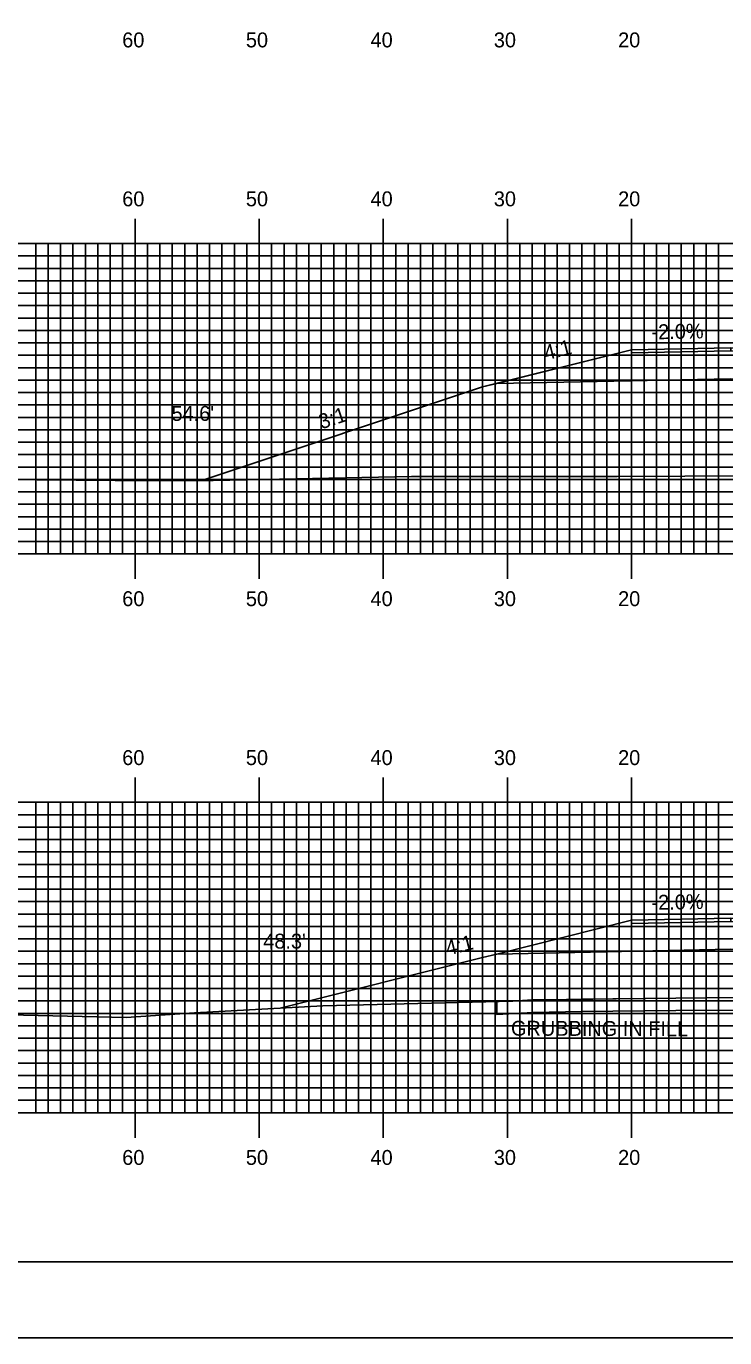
# Model space of a CAD drawing. Extents: x 1814915 to 1815259, y 442591 to 442811.
# Drawn here: x 1815012.3 to 1815068.5, y 442590.5 to 442696.2 of the extents above; entities that cross this region are included whole.
import ezdxf

# ---------------------------------------------------------------- set-up
doc = ezdxf.new("R2010")
doc.units = 0
for name, color, linetype in [('ANNOTATION', 7, 'Continuous'), ('BORDER', 7, 'Continuous'), ('D_Roadway_Centerline', 7, 'Continuous'), ('D_Roadway_Edge_Shoulder', 7, 'Continuous'), ('D_Roadway_SlopeLines', 7, 'Continuous'), ('D_Roadway_SubGrade', 7, 'Continuous'), ('D_Text_Standard', 7, 'Continuous'), ('GRUBBING IN FILL', 7, 'Continuous'), ('H_V ANNOTATION', 7, 'Continuous'), ('MAJOR', 7, 'Continuous'), ('MINOR', 7, 'Continuous'), ('PLOT BOUNDARY', 7, 'Continuous'), ('S_Roadway_Centerline', 7, 'Continuous')]:
    doc.layers.add(name, color=color, linetype=linetype)

msp = doc.modelspace()

# ---------------------------------------------------------------- linework, layer by layer
at = {"layer": 'BORDER'}
msp.add_lwpolyline([(1814931.42, 442596.67), (1815251.42, 442596.67), (1815251.42, 442806.67), (1814931.42, 442806.67)], close=True, dxfattribs=at)
at = {"layer": 'D_Roadway_Centerline'}
for points in [[(1815026.39, 442659.58), (1815049.02, 442667.12), (1815050.15, 442667.4), (1815061.02, 442670.12), (1815069.02, 442670.28), (1815081.02, 442669.7), (1815093.02, 442669.13), (1815101.02, 442668.74), (1815113.02, 442665.74), (1815113.4, 442665.65), (1815128.52, 442660.58)], [(1815032.71, 442617.09), (1815049.02, 442621.17), (1815050.15, 442621.45), (1815061.02, 442624.17), (1815069.02, 442624.33), (1815081.02, 442623.75), (1815093.02, 442623.17), (1815101.02, 442622.79), (1815113.4, 442619.7), (1815123.45, 442617.18)]]:
    msp.add_lwpolyline(points, dxfattribs=at)
at = {"layer": 'D_Roadway_Edge_Shoulder'}
for points in [[(1815069.02, 442670.28), (1815061.02, 442670.12), (1815061.02, 442669.87), (1815069.02, 442670.03)], [(1815069.02, 442624.33), (1815061.02, 442624.17), (1815061.02, 442623.92), (1815069.02, 442624.08)]]:
    msp.add_lwpolyline(points, close=True, dxfattribs=at)
at = {"layer": 'D_Roadway_SlopeLines'}
for points in [[(1815061.02, 442670.12), (1815049.02, 442667.12), (1815026.39, 442659.58)], [(1815061.02, 442624.17), (1815050.15, 442621.45), (1815049.02, 442621.17), (1815032.71, 442617.09)]]:
    msp.add_lwpolyline(points, dxfattribs=at)
at = {"layer": 'D_Roadway_SubGrade'}
for points in [[(1815069.02, 442667.78), (1815050.15, 442667.4), (1815061.02, 442670.12), (1815061.02, 442669.87), (1815069.02, 442670.03), (1815081.02, 442669.45), (1815093.02, 442668.88), (1815101.02, 442668.49), (1815101.02, 442668.74), (1815113.4, 442665.65), (1815093.02, 442666.63), (1815081.02, 442667.2)], [(1815069.02, 442621.83), (1815050.15, 442621.45), (1815061.02, 442624.17), (1815061.02, 442623.92), (1815069.02, 442624.08), (1815081.02, 442623.5), (1815093.02, 442622.92), (1815101.02, 442622.54), (1815101.02, 442622.79), (1815113.4, 442619.7), (1815093.02, 442620.67), (1815081.02, 442621.25)]]:
    msp.add_lwpolyline(points, close=True, dxfattribs=at)
at = {"layer": 'GRUBBING IN FILL'}
msp.add_lwpolyline([(1815050.15, 442617.63), (1815052.24, 442617.71), (1815056.96, 442617.81), (1815064.58, 442617.9), (1815069.39, 442617.94), (1815075.61, 442617.88), (1815081.02, 442617.84), (1815081.02, 442616.84), (1815075.61, 442616.88), (1815069.39, 442616.94), (1815064.59, 442616.9), (1815056.98, 442616.81), (1815053.08, 442616.75), (1815050.15, 442616.59)], close=True, dxfattribs=at)
msp.add_lwpolyline([(1815050.15, 442617.63), (1815052.24, 442617.71), (1815056.96, 442617.81), (1815064.58, 442617.9), (1815069.39, 442617.94), (1815075.61, 442617.88), (1815081.02, 442617.84), (1815081.02, 442616.84), (1815075.61, 442616.88), (1815069.39, 442616.94), (1815064.59, 442616.9), (1815056.98, 442616.81), (1815053.08, 442616.75), (1815050.15, 442616.59)], close=True, dxfattribs=at)
at = {"layer": 'MAJOR'}
for p, q in [((1815021.02, 442680.67), (1815021.02, 442678.67)), ((1815031.02, 442680.67), (1815031.02, 442678.67)), ((1815041.02, 442680.67), (1815041.02, 442678.67)), ((1815051.02, 442680.67), (1815051.02, 442678.67)), ((1815061.02, 442680.67), (1815061.02, 442678.67)), ((1814941.02, 442678.67), (1815221.02, 442678.67)), ((1814941.02, 442678.67), (1815221.02, 442678.67)), ((1815021.02, 442653.67), (1815021.02, 442678.67)), ((1815031.02, 442653.67), (1815031.02, 442678.67)), ((1815041.02, 442653.67), (1815041.02, 442678.67)), ((1815051.02, 442653.67), (1815051.02, 442678.67)), ((1815061.02, 442653.67), (1815061.02, 442678.67)), ((1814941.02, 442673.67), (1815221.02, 442673.67)), ((1814941.02, 442668.67), (1815221.02, 442668.67)), ((1814941.02, 442663.67), (1815221.02, 442663.67)), ((1814941.02, 442658.67), (1815221.02, 442658.67)), ((1814941.02, 442653.67), (1815221.02, 442653.67)), ((1814941.02, 442653.67), (1815221.02, 442653.67)), ((1815021.02, 442651.66), (1815021.02, 442653.67)), ((1815031.02, 442651.66), (1815031.02, 442653.67)), ((1815041.02, 442651.66), (1815041.02, 442653.67)), ((1815051.02, 442651.66), (1815051.02, 442653.67)), ((1815061.02, 442651.66), (1815061.02, 442653.67)), ((1815021.02, 442635.67), (1815021.02, 442633.67)), ((1815031.02, 442635.67), (1815031.02, 442633.67)), ((1815041.02, 442635.67), (1815041.02, 442633.67)), ((1815051.02, 442635.67), (1815051.02, 442633.67)), ((1815061.02, 442635.67), (1815061.02, 442633.67)), ((1814941.02, 442633.67), (1815221.02, 442633.67)), ((1814941.02, 442633.67), (1815221.02, 442633.67)), ((1815021.02, 442608.67), (1815021.02, 442633.67)), ((1815031.02, 442608.67), (1815031.02, 442633.67)), ((1815041.02, 442608.67), (1815041.02, 442633.67)), ((1815051.02, 442608.67), (1815051.02, 442633.67)), ((1815061.02, 442608.67), (1815061.02, 442633.67)), ((1814941.02, 442628.67), (1815221.02, 442628.67)), ((1814941.02, 442623.67), (1815221.02, 442623.67)), ((1814941.02, 442618.67), (1815221.02, 442618.67)), ((1814941.02, 442613.67), (1815221.02, 442613.67)), ((1814941.02, 442608.67), (1815221.02, 442608.67)), ((1814941.02, 442608.67), (1815221.02, 442608.67)), ((1815021.02, 442606.66), (1815021.02, 442608.67)), ((1815031.02, 442606.66), (1815031.02, 442608.67)), ((1815041.02, 442606.66), (1815041.02, 442608.67)), ((1815051.02, 442606.66), (1815051.02, 442608.67)), ((1815061.02, 442606.66), (1815061.02, 442608.67))]:
    msp.add_line(p, q, dxfattribs=at)
at = {"layer": 'MINOR'}
for p, q in [((1815013.02, 442653.67), (1815013.02, 442678.67)), ((1815014.02, 442653.67), (1815014.02, 442678.67)), ((1815015.02, 442653.67), (1815015.02, 442678.67)), ((1815016.02, 442653.67), (1815016.02, 442678.67)), ((1815017.02, 442653.67), (1815017.02, 442678.67)), ((1815018.02, 442653.67), (1815018.02, 442678.67)), ((1815019.02, 442653.67), (1815019.02, 442678.67)), ((1815020.02, 442653.67), (1815020.02, 442678.67)), ((1815022.02, 442653.67), (1815022.02, 442678.67)), ((1815023.02, 442653.67), (1815023.02, 442678.67)), ((1815024.02, 442653.67), (1815024.02, 442678.67)), ((1815025.02, 442653.67), (1815025.02, 442678.67)), ((1815026.02, 442653.67), (1815026.02, 442678.67)), ((1815027.02, 442653.67), (1815027.02, 442678.67)), ((1815028.02, 442653.67), (1815028.02, 442678.67)), ((1815029.02, 442653.67), (1815029.02, 442678.67)), ((1815030.02, 442653.67), (1815030.02, 442678.67)), ((1815032.02, 442653.67), (1815032.02, 442678.67)), ((1815033.02, 442653.67), (1815033.02, 442678.67)), ((1815034.02, 442653.67), (1815034.02, 442678.67)), ((1815035.02, 442653.67), (1815035.02, 442678.67)), ((1815036.02, 442653.67), (1815036.02, 442678.67)), ((1815037.02, 442653.67), (1815037.02, 442678.67)), ((1815038.02, 442653.67), (1815038.02, 442678.67)), ((1815039.02, 442653.67), (1815039.02, 442678.67)), ((1815040.02, 442653.67), (1815040.02, 442678.67)), ((1815042.02, 442653.67), (1815042.02, 442678.67)), ((1815043.02, 442653.67), (1815043.02, 442678.67)), ((1815044.02, 442653.67), (1815044.02, 442678.67)), ((1815045.02, 442653.67), (1815045.02, 442678.67)), ((1815046.02, 442653.67), (1815046.02, 442678.67)), ((1815047.02, 442653.67), (1815047.02, 442678.67)), ((1815048.02, 442653.67), (1815048.02, 442678.67)), ((1815049.02, 442653.67), (1815049.02, 442678.67)), ((1815050.02, 442653.67), (1815050.02, 442678.67)), ((1815052.02, 442653.67), (1815052.02, 442678.67)), ((1815053.02, 442653.67), (1815053.02, 442678.67)), ((1815054.02, 442653.67), (1815054.02, 442678.67)), ((1815055.02, 442653.67), (1815055.02, 442678.67)), ((1815056.02, 442653.67), (1815056.02, 442678.67)), ((1815057.02, 442653.67), (1815057.02, 442678.67)), ((1815058.02, 442653.67), (1815058.02, 442678.67)), ((1815059.02, 442653.67), (1815059.02, 442678.67)), ((1815060.02, 442653.67), (1815060.02, 442678.67)), ((1815062.02, 442653.67), (1815062.02, 442678.67)), ((1815063.02, 442653.67), (1815063.02, 442678.67)), ((1815064.02, 442653.67), (1815064.02, 442678.67)), ((1815065.02, 442653.67), (1815065.02, 442678.67)), ((1815066.02, 442653.67), (1815066.02, 442678.67)), ((1815067.02, 442653.67), (1815067.02, 442678.67)), ((1815068.02, 442653.67), (1815068.02, 442678.67)), ((1814941.02, 442677.67), (1815221.02, 442677.67)), ((1814941.02, 442676.67), (1815221.02, 442676.67)), ((1814941.02, 442675.67), (1815221.02, 442675.67)), ((1814941.02, 442674.67), (1815221.02, 442674.67)), ((1814941.02, 442672.67), (1815221.02, 442672.67)), ((1814941.02, 442671.67), (1815221.02, 442671.67)), ((1814941.02, 442670.67), (1815221.02, 442670.67)), ((1814941.02, 442669.67), (1815221.02, 442669.67)), ((1814941.02, 442667.67), (1815221.02, 442667.67)), ((1814941.02, 442666.67), (1815221.02, 442666.67)), ((1814941.02, 442665.67), (1815221.02, 442665.67)), ((1814941.02, 442664.67), (1815221.02, 442664.67)), ((1814941.02, 442662.67), (1815221.02, 442662.67)), ((1814941.02, 442661.67), (1815221.02, 442661.67)), ((1814941.02, 442660.67), (1815221.02, 442660.67)), ((1814941.02, 442659.67), (1815221.02, 442659.67)), ((1814941.02, 442657.67), (1815221.02, 442657.67)), ((1814941.02, 442656.67), (1815221.02, 442656.67)), ((1814941.02, 442655.67), (1815221.02, 442655.67)), ((1814941.02, 442654.67), (1815221.02, 442654.67)), ((1815013.02, 442608.67), (1815013.02, 442633.67)), ((1815014.02, 442608.67), (1815014.02, 442633.67)), ((1815015.02, 442608.67), (1815015.02, 442633.67)), ((1815016.02, 442608.67), (1815016.02, 442633.67)), ((1815017.02, 442608.67), (1815017.02, 442633.67)), ((1815018.02, 442608.67), (1815018.02, 442633.67)), ((1815019.02, 442608.67), (1815019.02, 442633.67)), ((1815020.02, 442608.67), (1815020.02, 442633.67)), ((1815022.02, 442608.67), (1815022.02, 442633.67)), ((1815023.02, 442608.67), (1815023.02, 442633.67)), ((1815024.02, 442608.67), (1815024.02, 442633.67)), ((1815025.02, 442608.67), (1815025.02, 442633.67)), ((1815026.02, 442608.67), (1815026.02, 442633.67)), ((1815027.02, 442608.67), (1815027.02, 442633.67)), ((1815028.02, 442608.67), (1815028.02, 442633.67)), ((1815029.02, 442608.67), (1815029.02, 442633.67)), ((1815030.02, 442608.67), (1815030.02, 442633.67)), ((1815032.02, 442608.67), (1815032.02, 442633.67)), ((1815033.02, 442608.67), (1815033.02, 442633.67)), ((1815034.02, 442608.67), (1815034.02, 442633.67)), ((1815035.02, 442608.67), (1815035.02, 442633.67)), ((1815036.02, 442608.67), (1815036.02, 442633.67)), ((1815037.02, 442608.67), (1815037.02, 442633.67)), ((1815038.02, 442608.67), (1815038.02, 442633.67)), ((1815039.02, 442608.67), (1815039.02, 442633.67)), ((1815040.02, 442608.67), (1815040.02, 442633.67)), ((1815042.02, 442608.67), (1815042.02, 442633.67)), ((1815043.02, 442608.67), (1815043.02, 442633.67)), ((1815044.02, 442608.67), (1815044.02, 442633.67)), ((1815045.02, 442608.67), (1815045.02, 442633.67)), ((1815046.02, 442608.67), (1815046.02, 442633.67)), ((1815047.02, 442608.67), (1815047.02, 442633.67)), ((1815048.02, 442608.67), (1815048.02, 442633.67)), ((1815049.02, 442608.67), (1815049.02, 442633.67)), ((1815050.02, 442608.67), (1815050.02, 442633.67)), ((1815052.02, 442608.67), (1815052.02, 442633.67)), ((1815053.02, 442608.67), (1815053.02, 442633.67)), ((1815054.02, 442608.67), (1815054.02, 442633.67)), ((1815055.02, 442608.67), (1815055.02, 442633.67)), ((1815056.02, 442608.67), (1815056.02, 442633.67)), ((1815057.02, 442608.67), (1815057.02, 442633.67)), ((1815058.02, 442608.67), (1815058.02, 442633.67)), ((1815059.02, 442608.67), (1815059.02, 442633.67)), ((1815060.02, 442608.67), (1815060.02, 442633.67)), ((1815062.02, 442608.67), (1815062.02, 442633.67)), ((1815063.02, 442608.67), (1815063.02, 442633.67)), ((1815064.02, 442608.67), (1815064.02, 442633.67)), ((1815065.02, 442608.67), (1815065.02, 442633.67)), ((1815066.02, 442608.67), (1815066.02, 442633.67)), ((1815067.02, 442608.67), (1815067.02, 442633.67)), ((1815068.02, 442608.67), (1815068.02, 442633.67)), ((1814941.02, 442632.67), (1815221.02, 442632.67)), ((1814941.02, 442631.67), (1815221.02, 442631.67)), ((1814941.02, 442630.67), (1815221.02, 442630.67)), ((1814941.02, 442629.67), (1815221.02, 442629.67)), ((1814941.02, 442627.67), (1815221.02, 442627.67)), ((1814941.02, 442626.67), (1815221.02, 442626.67)), ((1814941.02, 442625.67), (1815221.02, 442625.67)), ((1814941.02, 442624.67), (1815221.02, 442624.67)), ((1814941.02, 442622.67), (1815221.02, 442622.67)), ((1814941.02, 442621.67), (1815221.02, 442621.67)), ((1814941.02, 442620.67), (1815221.02, 442620.67)), ((1814941.02, 442619.67), (1815221.02, 442619.67)), ((1814941.02, 442617.67), (1815221.02, 442617.67)), ((1814941.02, 442616.67), (1815221.02, 442616.67)), ((1814941.02, 442615.67), (1815221.02, 442615.67)), ((1814941.02, 442614.67), (1815221.02, 442614.67)), ((1814941.02, 442612.67), (1815221.02, 442612.67)), ((1814941.02, 442611.67), (1815221.02, 442611.67)), ((1814941.02, 442610.67), (1815221.02, 442610.67)), ((1814941.02, 442609.67), (1815221.02, 442609.67))]:
    msp.add_line(p, q, dxfattribs=at)
at = {"layer": 'PLOT BOUNDARY'}
msp.add_lwpolyline([(1814915.23, 442590.55), (1815255.23, 442590.55), (1815255.23, 442810.55), (1814915.23, 442810.55)], close=True, dxfattribs=at)
at = {"layer": 'S_Roadway_Centerline'}
for points in [[(1815009.96, 442659.68), (1815019.41, 442659.59), (1815026, 442659.57), (1815036.63, 442659.78), (1815043.29, 442659.91), (1815058.79, 442659.92), (1815059.86, 442659.91), (1815065.31, 442659.94), (1815076.02, 442659.96), (1815088.76, 442659.95), (1815094.39, 442660.23), (1815101.84, 442660.54), (1815111.09, 442660.6), (1815117.76, 442660.81), (1815141.21, 442660.3)], [(1815010.86, 442616.56), (1815020.3, 442616.33), (1815025.82, 442616.72), (1815036.15, 442617.27), (1815051.44, 442617.66), (1815053.04, 442617.75), (1815054.16, 442617.77), (1815059.77, 442617.85), (1815069.39, 442617.94), (1815081.83, 442617.83), (1815086, 442617.75), (1815097.63, 442617.4), (1815103.62, 442617.3), (1815107.42, 442617.12), (1815125.62, 442617.19), (1815135.82, 442617.07), (1815152.82, 442616.3)]]:
    msp.add_lwpolyline(points, dxfattribs=at)

# ---------------------------------------------------------------- texts
at = {"layer": 'ANNOTATION'}
for s, rotation, p in [('-2.0%', 1.1458, (1815062.63, 442670.95)), ('4:1', 14.0362, (1815054.12, 442669.26)), ('3:1', 18.4348, (1815036.04, 442663.7)), ('-2.0%', 1.1458, (1815062.63, 442625)), ('4:1', 14.0362, (1815046.2, 442621.32))]:
    msp.add_text(s, height=1.2, rotation=rotation, dxfattribs=at).set_placement(p)
at = {"layer": 'D_Text_Standard'}
for s, p in [("54.6'", (1815023.96, 442664.39)), ("48.3'", (1815031.35, 442621.89))]:
    msp.add_text(s, height=1.2, dxfattribs=at).set_placement(p)
at = {"layer": 'GRUBBING IN FILL'}
msp.add_text('GRUBBING IN FILL', height=1.2, rotation=359.8053, dxfattribs=at).set_placement((1815051.3, 442614.88))
at = {"layer": 'H_V ANNOTATION'}
for s, p in [('60', (1815019.99, 442694.47)), ('50', (1815029.95, 442694.47)), ('40', (1815039.99, 442694.47)), ('30', (1815049.92, 442694.47)), ('20', (1815059.93, 442694.47)), ('60', (1815019.99, 442681.67)), ('50', (1815029.95, 442681.67)), ('40', (1815039.99, 442681.67)), ('30', (1815049.92, 442681.67)), ('20', (1815059.93, 442681.67)), ('60', (1815019.99, 442649.47)), ('50', (1815029.95, 442649.47)), ('40', (1815039.99, 442649.47)), ('30', (1815049.92, 442649.47)), ('20', (1815059.93, 442649.47)), ('60', (1815019.99, 442636.67)), ('50', (1815029.95, 442636.67)), ('40', (1815039.99, 442636.67)), ('30', (1815049.92, 442636.67)), ('20', (1815059.93, 442636.67)), ('60', (1815019.99, 442604.47)), ('50', (1815029.95, 442604.47)), ('40', (1815039.99, 442604.47)), ('30', (1815049.92, 442604.47)), ('20', (1815059.93, 442604.47))]:
    msp.add_text(s, height=1.2, dxfattribs=at).set_placement(p)

doc.saveas('drawing.dxf')
